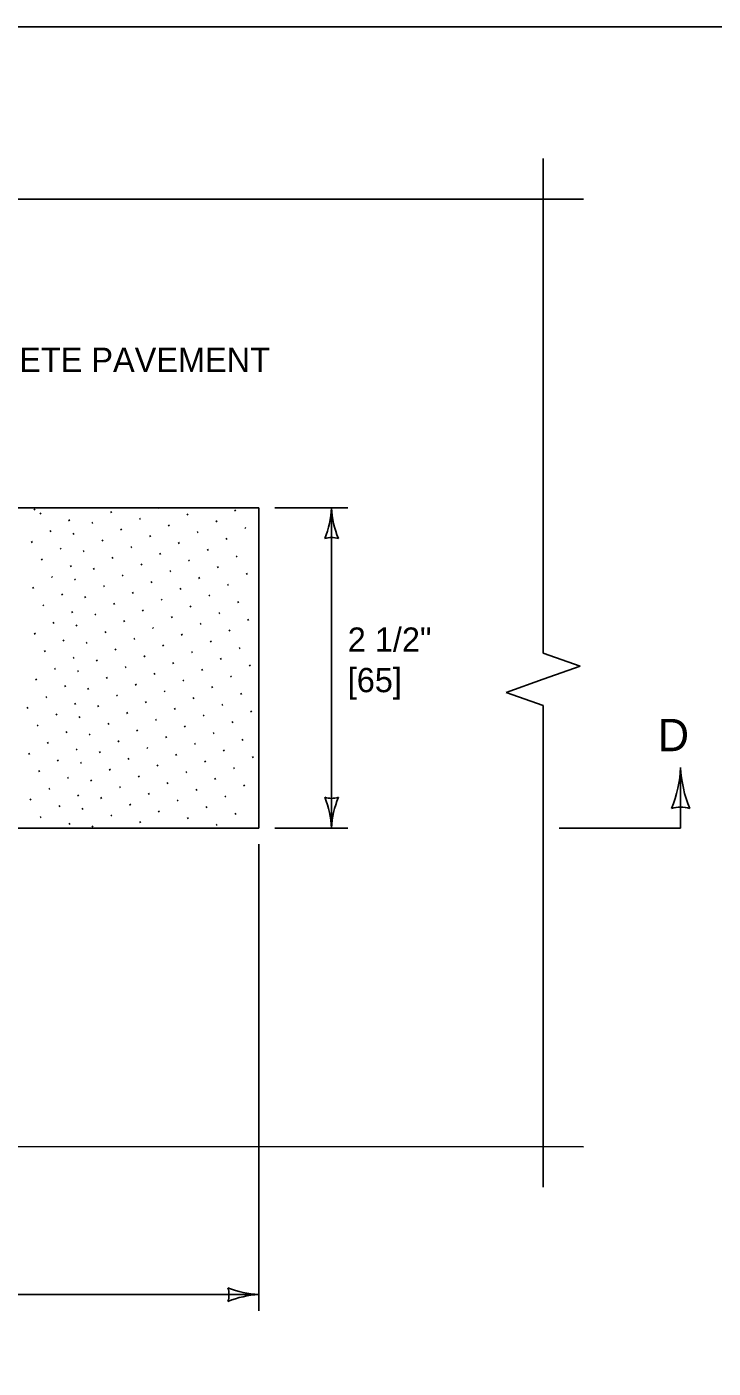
# Model space of a CAD drawing. Extents: x 49991.4 to 50021, y 49987.6 to 50011.4.
# Drawn here: x 50013.04 to 50014.736, y 49995.683 to 49998.999 of the extents above; entities that cross this region are included whole.
import ezdxf

# ---------------------------------------------------------------- set-up
doc = ezdxf.new("R2010")
doc.units = 0
for name, color, linetype in [('Level 1', 7, 'Continuous'), ('Level 2', 7, 'Continuous'), ('Level 3', 7, 'Continuous'), ('Level 6', 7, 'Continuous')]:
    doc.layers.add(name, color=color, linetype=linetype)

msp = doc.modelspace()

# ---------------------------------------------------------------- linework, layer by layer
at = {"layer": 'Level 1'}
for p, q in [((50002.4589, 49997.8102), (50013.6129, 49997.8102)), ((50013.6129, 49997.8102), (50013.6129, 49997.0183)), ((50013.6129, 49997.0183), (50002.4589, 49997.0183))]:
    msp.add_line(p, q, dxfattribs=at)
msp.add_lwpolyline([(49999.3835, 49998.9992), (50016.7501, 49998.9992), (50016.7501, 49987.7988), (49999.3835, 49987.7988)], close=True, dxfattribs=at)
at = {"layer": 'Level 3'}
for p, q in [((50013.0574, 49997.805), (50013.0604, 49997.8067)), ((50013.3641, 49997.8088), (50013.3665, 49997.8102)), ((50013.5531, 49997.8025), (50013.5562, 49997.8043)), ((50013.6529, 49997.8102), (50013.8328, 49997.8102)), ((50013.7928, 49997.8102), (50013.7928, 49997.0183)), ((50013.0718, 49997.7948), (50013.0748, 49997.7965)), ((50013.1431, 49997.7782), (50013.1461, 49997.78)), ((50013.2001, 49997.7719), (50013.2031, 49997.7736)), ((50013.2464, 49997.7986), (50013.2495, 49997.8004)), ((50013.3178, 49997.7821), (50013.3208, 49997.7838)), ((50013.4354, 49997.7923), (50013.4385, 49997.794)), ((50013.5068, 49997.7757), (50013.5098, 49997.7775)), ((50013.0968, 49997.7515), (50013.0998, 49997.7532)), ((50013.1538, 49997.7451), (50013.1568, 49997.7469)), ((50013.2714, 49997.7553), (50013.2745, 49997.7571)), ((50013.3428, 49997.7388), (50013.3458, 49997.7405)), ((50013.3891, 49997.7655), (50013.3921, 49997.7673)), ((50013.4604, 49997.749), (50013.4635, 49997.7507)), ((50013.5781, 49997.7592), (50013.5812, 49997.761)), ((50013.0504, 49997.7247), (50013.0534, 49997.7265)), ((50013.1218, 49997.7082), (50013.1248, 49997.7099)), ((50013.1788, 49997.7018), (50013.1818, 49997.7036)), ((50013.2251, 49997.7286), (50013.2281, 49997.7303)), ((50013.2964, 49997.712), (50013.2995, 49997.7138)), ((50013.4141, 49997.7222), (50013.4171, 49997.724)), ((50013.4854, 49997.7057), (50013.4885, 49997.7074)), ((50013.5318, 49997.7324), (50013.5348, 49997.7342)), ((50013.0754, 49997.6814), (50013.0784, 49997.6832)), ((50013.2501, 49997.6853), (50013.2531, 49997.687)), ((50013.3214, 49997.6687), (50013.3245, 49997.6705)), ((50013.3678, 49997.6955), (50013.3708, 49997.6972)), ((50013.4391, 49997.6789), (50013.4421, 49997.6807)), ((50013.5568, 49997.6891), (50013.5598, 49997.6909)), ((50013.1004, 49997.6381), (50013.1034, 49997.6399)), ((50013.1468, 49997.6649), (50013.1498, 49997.6666)), ((50013.2038, 49997.6585), (50013.2068, 49997.6603)), ((50013.2751, 49997.642), (50013.2781, 49997.6437)), ((50013.3928, 49997.6522), (50013.3958, 49997.6539)), ((50013.4641, 49997.6356), (50013.4671, 49997.6374)), ((50013.5104, 49997.6624), (50013.5135, 49997.6641)), ((50013.5818, 49997.6458), (50013.5848, 49997.6476)), ((50013.0541, 49997.6114), (50013.0571, 49997.6131)), ((50013.1574, 49997.6318), (50013.1604, 49997.6335)), ((50013.2288, 49997.6152), (50013.2318, 49997.617)), ((50013.3464, 49997.6254), (50013.3495, 49997.6272)), ((50013.4178, 49997.6089), (50013.4208, 49997.6106)), ((50013.5354, 49997.6191), (50013.5385, 49997.6208)), ((50013.0791, 49997.5681), (50013.0821, 49997.5698)), ((50013.1254, 49997.5948), (50013.1284, 49997.5966)), ((50013.1824, 49997.5885), (50013.1854, 49997.5902)), ((50013.2538, 49997.5719), (50013.2568, 49997.5737)), ((50013.3001, 49997.5987), (50013.3031, 49997.6004)), ((50013.3714, 49997.5821), (50013.3745, 49997.5839)), ((50013.4891, 49997.5923), (50013.4921, 49997.5941)), ((50013.5604, 49997.5758), (50013.5635, 49997.5775)), ((50013.1504, 49997.5515), (50013.1534, 49997.5533)), ((50013.2074, 49997.5452), (50013.2104, 49997.5469)), ((50013.3251, 49997.5554), (50013.3281, 49997.5571)), ((50013.3964, 49997.5388), (50013.3995, 49997.5406)), ((50013.4428, 49997.5656), (50013.4458, 49997.5673)), ((50013.5141, 49997.549), (50013.5171, 49997.5508)), ((50013.1041, 49997.5248), (50013.1071, 49997.5265)), ((50013.1611, 49997.5184), (50013.1641, 49997.5202)), ((50013.2324, 49997.5019), (50013.2354, 49997.5036)), ((50013.2788, 49997.5286), (50013.2818, 49997.5304)), ((50013.3501, 49997.5121), (50013.3531, 49997.5138)), ((50013.4678, 49997.5223), (50013.4708, 49997.524)), ((50013.5391, 49997.5057), (50013.5421, 49997.5075)), ((50013.5854, 49997.5325), (50013.5885, 49997.5342)), ((50013.0577, 49997.498), (50013.0608, 49997.4998)), ((50013.1291, 49997.4815), (50013.1321, 49997.4832)), ((50013.1861, 49997.4751), (50013.1891, 49997.4769)), ((50013.3038, 49997.4853), (50013.3068, 49997.4871)), ((50013.3751, 49997.4688), (50013.3781, 49997.4705)), ((50013.4214, 49997.4955), (50013.4245, 49997.4973)), ((50013.4928, 49997.479), (50013.4958, 49997.4807)), ((50013.0827, 49997.4547), (50013.0858, 49997.4565)), ((50013.1541, 49997.4382), (50013.1571, 49997.4399)), ((50013.2574, 49997.4586), (50013.2604, 49997.4603)), ((50013.3288, 49997.442), (50013.3318, 49997.4438)), ((50013.4464, 49997.4522), (50013.4495, 49997.454)), ((50013.5178, 49997.4357), (50013.5208, 49997.4374)), ((50013.5641, 49997.4624), (50013.5671, 49997.4642)), ((50013.1077, 49997.4114), (50013.1108, 49997.4132)), ((50013.1647, 49997.4051), (50013.1678, 49997.4068)), ((50013.2111, 49997.4318), (50013.2141, 49997.4336)), ((50013.2824, 49997.4153), (50013.2854, 49997.417)), ((50013.4001, 49997.4255), (50013.4031, 49997.4272)), ((50013.4714, 49997.4089), (50013.4745, 49997.4107)), ((50013.5891, 49997.4191), (50013.5921, 49997.4209)), ((50013.0614, 49997.3847), (50013.0644, 49997.3864)), ((50013.2361, 49997.3885), (50013.2391, 49997.3903)), ((50013.3074, 49997.372), (50013.3104, 49997.3737)), ((50013.3538, 49997.3987), (50013.3568, 49997.4005)), ((50013.4251, 49997.3822), (50013.4281, 49997.3839)), ((50013.5428, 49997.3924), (50013.5458, 49997.3941)), ((50013.0864, 49997.3414), (50013.0894, 49997.3431)), ((50013.1327, 49997.3681), (50013.1358, 49997.3699)), ((50013.1897, 49997.3618), (50013.1928, 49997.3635)), ((50013.2611, 49997.3452), (50013.2641, 49997.347)), ((50013.3788, 49997.3554), (50013.3818, 49997.3572)), ((50013.4501, 49997.3389), (50013.4531, 49997.3406)), ((50013.4964, 49997.3656), (50013.4995, 49997.3674)), ((50013.5678, 49997.3491), (50013.5708, 49997.3508)), ((50013.0401, 49997.3146), (50013.0431, 49997.3163)), ((50013.1577, 49997.3248), (50013.1608, 49997.3266)), ((50013.2147, 49997.3185), (50013.2178, 49997.3202)), ((50013.3324, 49997.3287), (50013.3354, 49997.3304)), ((50013.4038, 49997.3121), (50013.4068, 49997.3139)), ((50013.5214, 49997.3223), (50013.5245, 49997.3241)), ((50013.5928, 49997.3058), (50013.5958, 49997.3075)), ((50013.0651, 49997.2713), (50013.0681, 49997.273)), ((50013.1114, 49997.298), (50013.1144, 49997.2998)), ((50013.1684, 49997.2917), (50013.1714, 49997.2935)), ((50013.2397, 49997.2752), (50013.2428, 49997.2769)), ((50013.2861, 49997.3019), (50013.2891, 49997.3037)), ((50013.3574, 49997.2854), (50013.3604, 49997.2871)), ((50013.4751, 49997.2956), (50013.4781, 49997.2973)), ((50013.5464, 49997.279), (50013.5495, 49997.2808)), ((50013.1364, 49997.2547), (50013.1394, 49997.2565)), ((50013.1934, 49997.2484), (50013.1964, 49997.2502)), ((50013.3111, 49997.2586), (50013.3141, 49997.2604)), ((50013.3824, 49997.2421), (50013.3854, 49997.2438)), ((50013.4288, 49997.2688), (50013.4318, 49997.2706)), ((50013.5001, 49997.2523), (50013.5031, 49997.254)), ((50013.0901, 49997.228), (50013.0931, 49997.2297)), ((50013.1614, 49997.2114), (50013.1644, 49997.2132)), ((50013.2184, 49997.2051), (50013.2214, 49997.2069)), ((50013.2647, 49997.2319), (50013.2678, 49997.2336)), ((50013.3361, 49997.2153), (50013.3391, 49997.2171)), ((50013.4538, 49997.2255), (50013.4568, 49997.2273)), ((50013.5251, 49997.209), (50013.5281, 49997.2107)), ((50013.5714, 49997.2357), (50013.5745, 49997.2375)), ((50013.0437, 49997.2012), (50013.0468, 49997.203)), ((50013.1151, 49997.1847), (50013.1181, 49997.1864)), ((50013.1721, 49997.1784), (50013.1751, 49997.1801)), ((50013.2897, 49997.1886), (50013.2928, 49997.1903)), ((50013.3611, 49997.172), (50013.3641, 49997.1738)), ((50013.4074, 49997.1988), (50013.4104, 49997.2005)), ((50013.4788, 49997.1822), (50013.4818, 49997.184)), ((50013.5964, 49997.1924), (50013.5995, 49997.1942)), ((50013.0687, 49997.1579), (50013.0718, 49997.1597)), ((50013.1401, 49997.1414), (50013.1431, 49997.1431)), ((50013.2434, 49997.1618), (50013.2464, 49997.1636)), ((50013.3147, 49997.1453), (50013.3178, 49997.147)), ((50013.4324, 49997.1555), (50013.4354, 49997.1572)), ((50013.5038, 49997.1389), (50013.5068, 49997.1407)), ((50013.5501, 49997.1657), (50013.5531, 49997.1674)), ((50013.0937, 49997.1146), (50013.0968, 49997.1164)), ((50013.1971, 49997.135), (50013.2001, 49997.1368)), ((50013.2684, 49997.1185), (50013.2714, 49997.1203)), ((50013.3861, 49997.1287), (50013.3891, 49997.1305)), ((50013.4574, 49997.1122), (50013.4604, 49997.1139)), ((50013.5751, 49997.1224), (50013.5781, 49997.1241)), ((50013.0474, 49997.0879), (50013.0504, 49997.0896)), ((50013.1187, 49997.0713), (50013.1218, 49997.0731)), ((50013.1651, 49997.0981), (50013.1681, 49997.0998)), ((50013.2221, 49997.0917), (50013.2251, 49997.0935)), ((50013.2934, 49997.0752), (50013.2964, 49997.077)), ((50013.3397, 49997.102), (50013.3428, 49997.1037)), ((50013.4111, 49997.0854), (50013.4141, 49997.0872)), ((50013.5288, 49997.0956), (50013.5318, 49997.0974)), ((50013.0724, 49997.0446), (50013.0754, 49997.0463)), ((50013.1757, 49997.065), (50013.1788, 49997.0667)), ((50013.2471, 49997.0484), (50013.2501, 49997.0502)), ((50013.3647, 49997.0587), (50013.3678, 49997.0604)), ((50013.4361, 49997.0421), (50013.4391, 49997.0439)), ((50013.4824, 49997.0689), (50013.4854, 49997.0706)), ((50013.5538, 49997.0523), (50013.5568, 49997.0541)), ((50013.1437, 49997.028), (50013.1468, 49997.0298)), ((50013.2007, 49997.0217), (50013.2038, 49997.0234)), ((50013.3184, 49997.0319), (50013.3214, 49997.0336)), ((50013.5074, 49997.0256), (50013.5104, 49997.0273)), ((50013.6529, 49997.0183), (50013.8328, 49997.0183)), ((50013.6129, 49996.9783), (50013.6129, 49995.8249)), ((50013.6132, 49995.8649), (50002.4589, 49995.8649))]:
    msp.add_line(p, q, dxfattribs=at)
for centre, radius, start, end in [((50013.5707, 49997.8194), 0.2223, 337.456, 357.6395), ((50014.0255, 49997.8217), 0.233, 182.8273, 202.0772), ((50013.7928, 49997.682), 0.0548, 72.1388, 107.8612), ((50014.3593, 49997.1805), 0.2964, 337.456, 357.6395), ((50014.9657, 49997.1836), 0.3107, 182.8273, 202.0772), ((50013.7928, 49997.1465), 0.0548, 252.1388, 287.8612), ((50013.5601, 49997.0068), 0.233, 2.8273, 22.0772), ((50014.015, 49997.0091), 0.2223, 157.456, 177.6395), ((50014.6554, 49996.9973), 0.073, 72.1388, 107.8612), ((50013.622, 49996.0871), 0.2223, 247.456, 267.6395), ((50013.4847, 49995.8649), 0.0548, 342.1388, 17.8612), ((50013.6244, 49995.6322), 0.233, 92.8273, 112.0772)]:
    msp.add_arc(centre, radius, start, end, dxfattribs=at)
at = {"layer": 'Level 6'}
for p, q in [((50014.3155, 49998.6733), (50014.3154, 49997.4509)), ((50014.4155, 49998.5732), (50011.5922, 49998.5733)), ((50014.4068, 49997.4185), (50014.3154, 49997.4509)), ((50014.4068, 49997.4185), (50014.3154, 49997.3861)), ((50014.3154, 49997.3861), (50014.224, 49997.3537)), ((50014.3154, 49997.3213), (50014.224, 49997.3537)), ((50014.3154, 49997.3213), (50014.3154, 49996.1307)), ((50014.6554, 49997.0183), (50014.6554, 49997.1683)), ((50014.6554, 49997.0183), (50014.3554, 49997.0183)), ((50014.4155, 49996.2306), (50011.5922, 49996.2307))]:
    msp.add_line(p, q, dxfattribs=at)

# ---------------------------------------------------------------- texts
at = {"layer": 'Level 2'}
for s, height, p in [('EXISTING CEMENT CONCRETE PAVEMENT', 0.06, (50011.9689, 49998.146)), ('2 1/2"', 0.06, (50013.8328, 49997.4542)), ('[65]', 0.06, (50013.8328, 49997.3542)), ('D', 0.08, (50014.599, 49997.2083))]:
    msp.add_text(s, height=height, dxfattribs=at).set_placement(p)

doc.saveas('drawing.dxf')
